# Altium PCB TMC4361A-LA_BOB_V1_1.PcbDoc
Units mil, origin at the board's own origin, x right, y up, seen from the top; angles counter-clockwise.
Board outline 1000 x 1500 mil, 4 copper layers (Top, GND1, GND2, Bottom), stack 27.719 mil thick; 21 components, 35 nets, 88 pads, 56 vias.
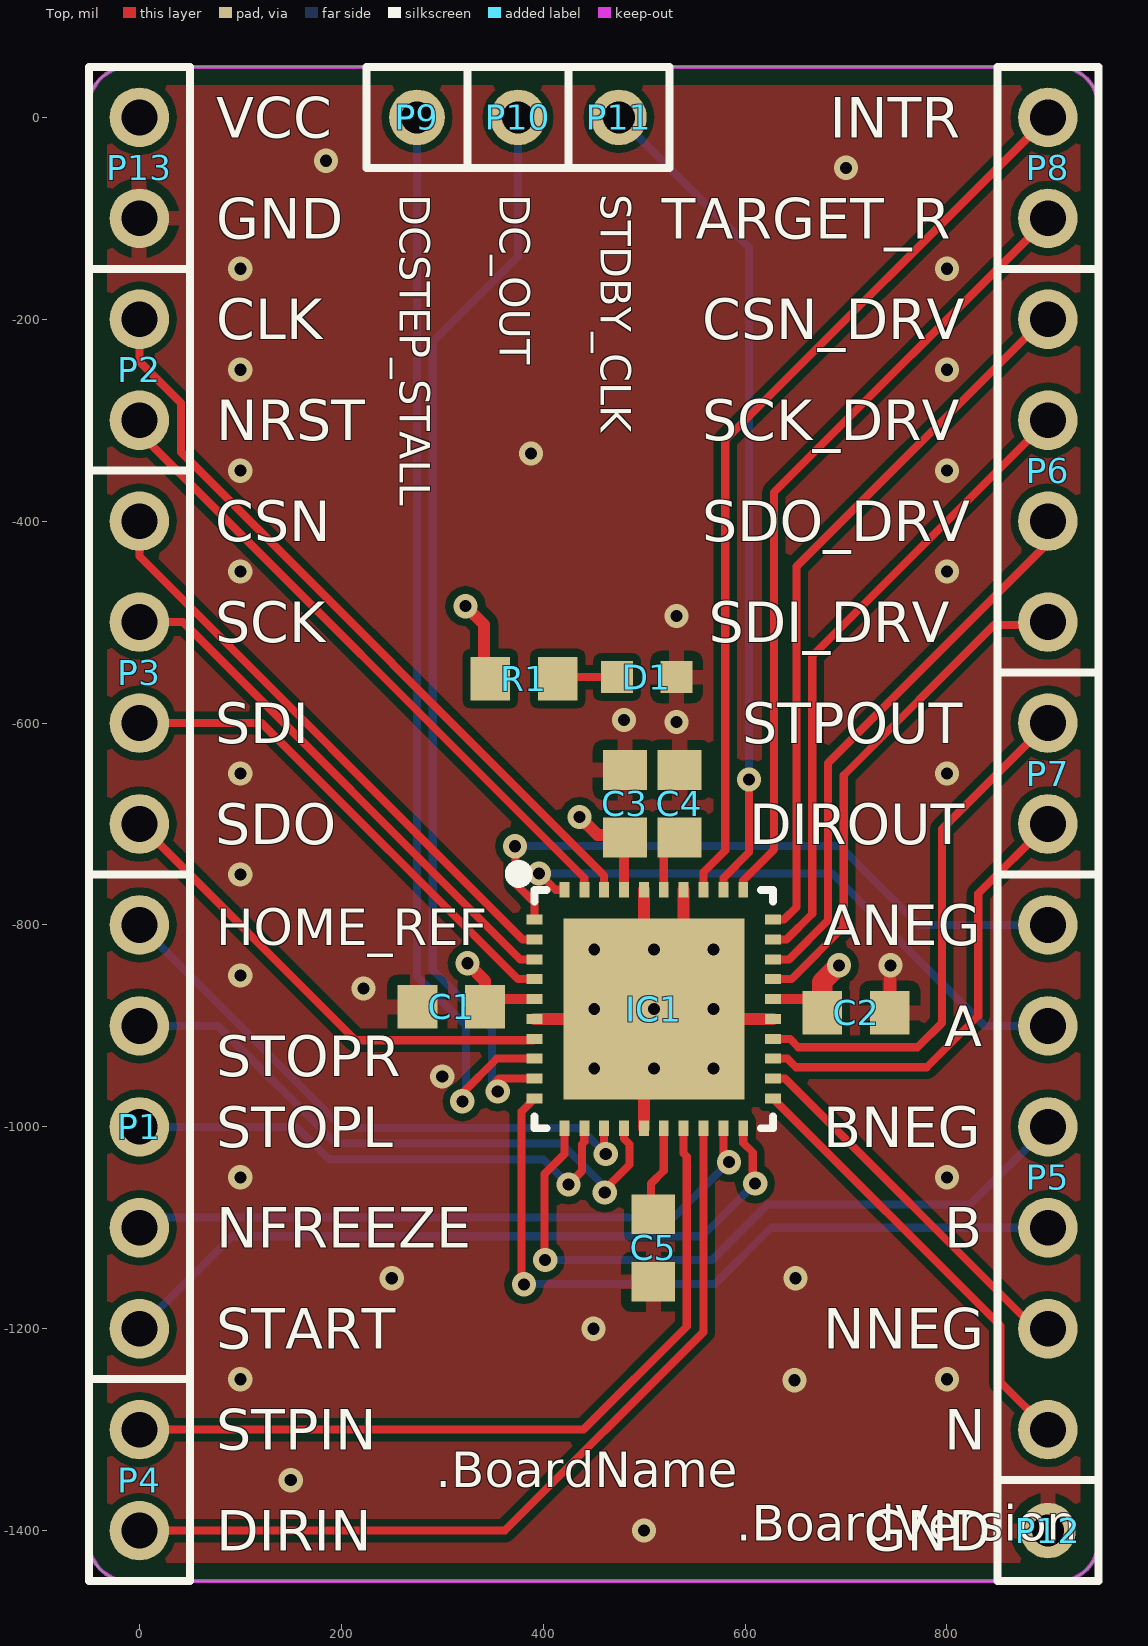
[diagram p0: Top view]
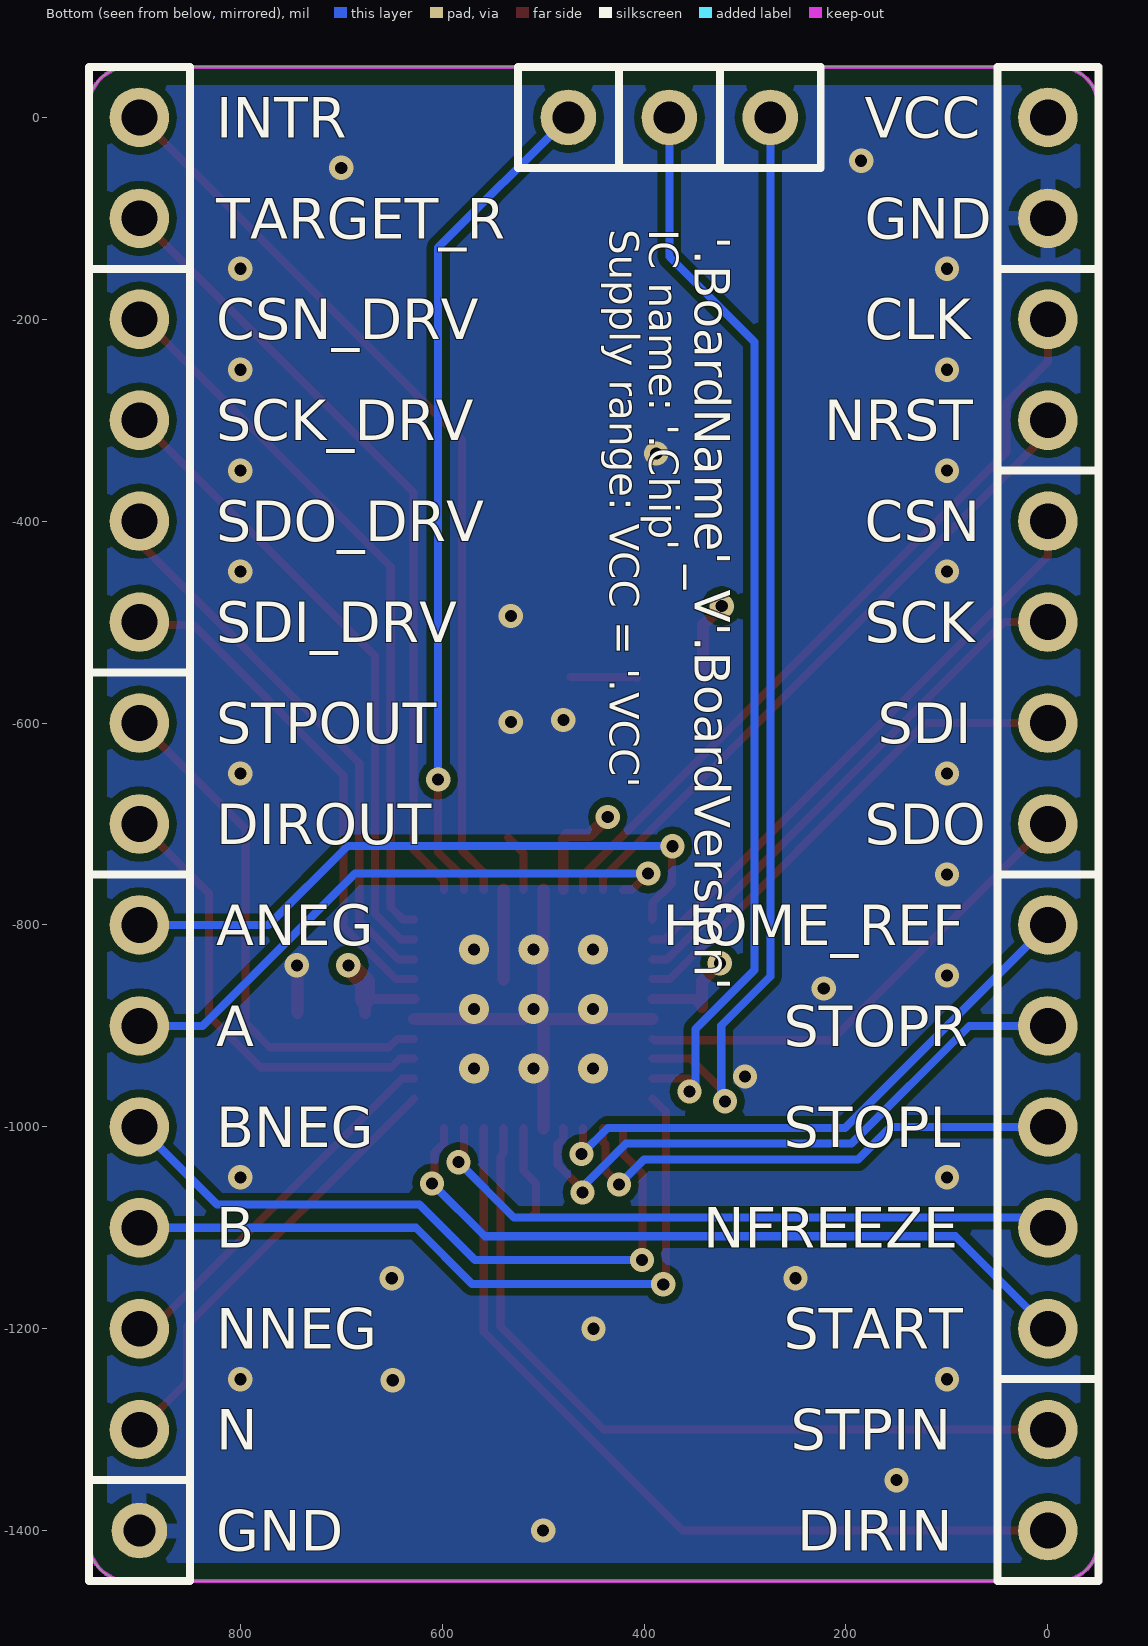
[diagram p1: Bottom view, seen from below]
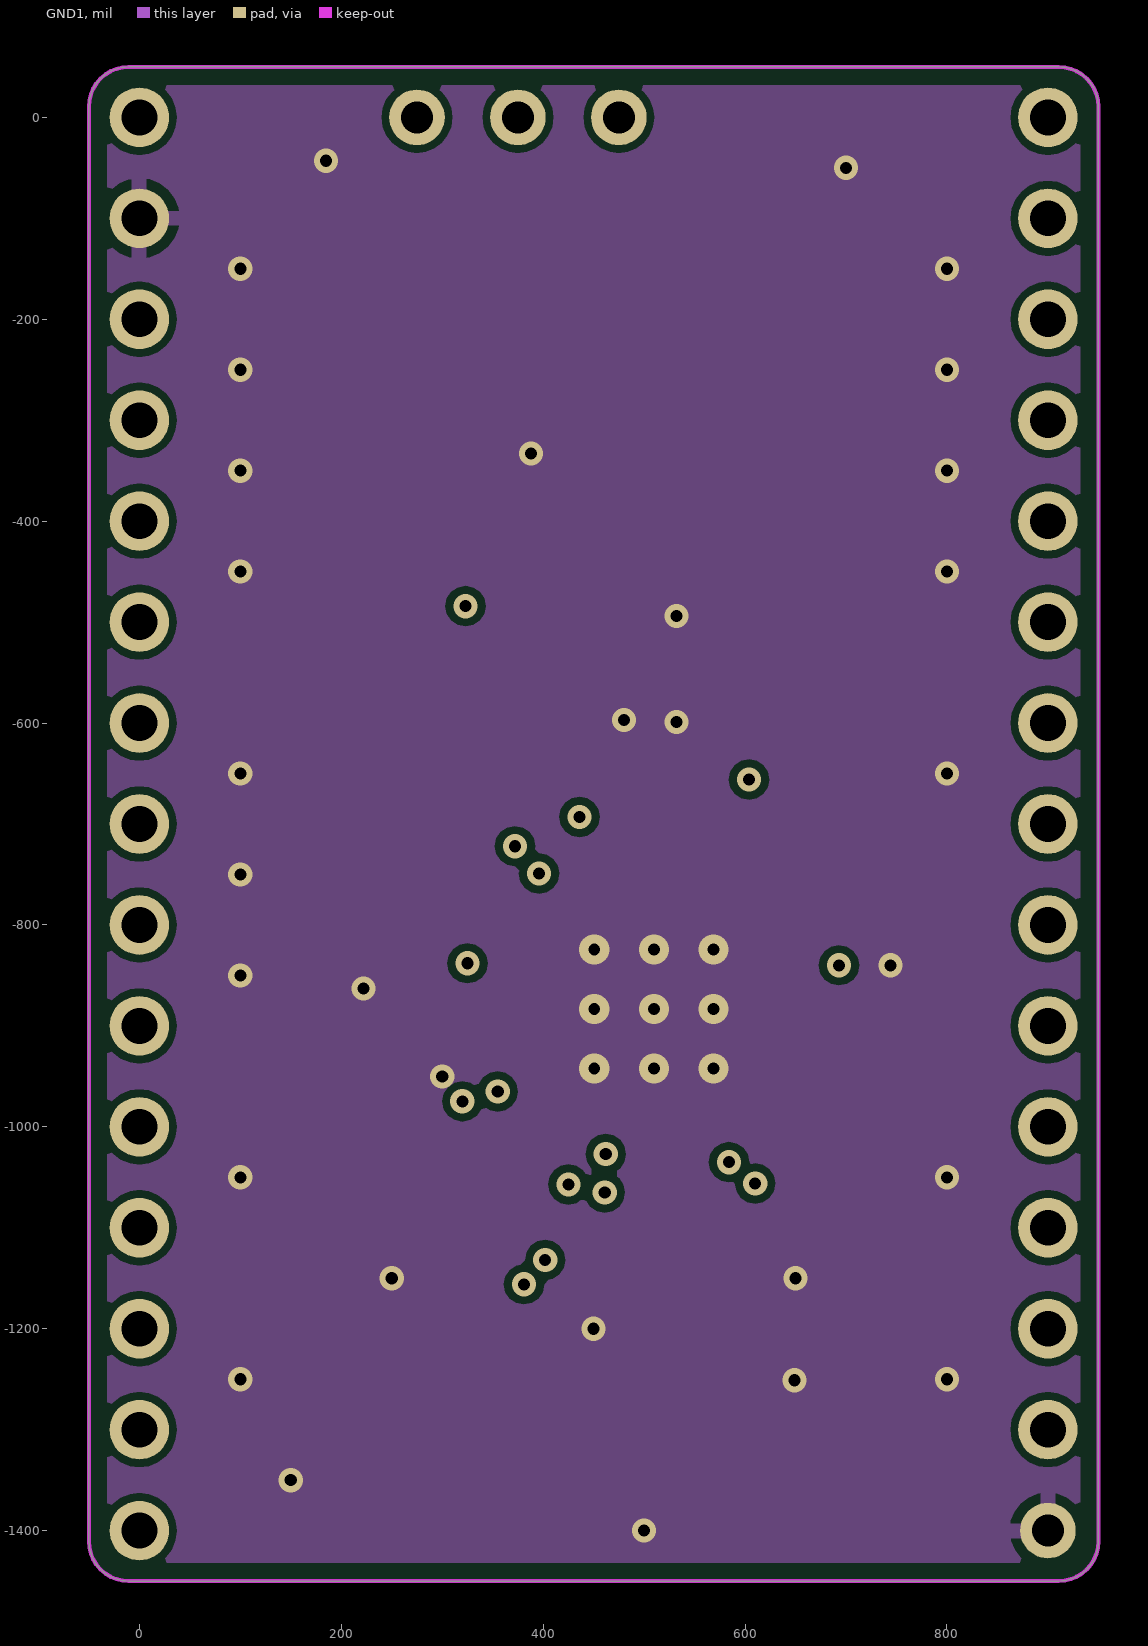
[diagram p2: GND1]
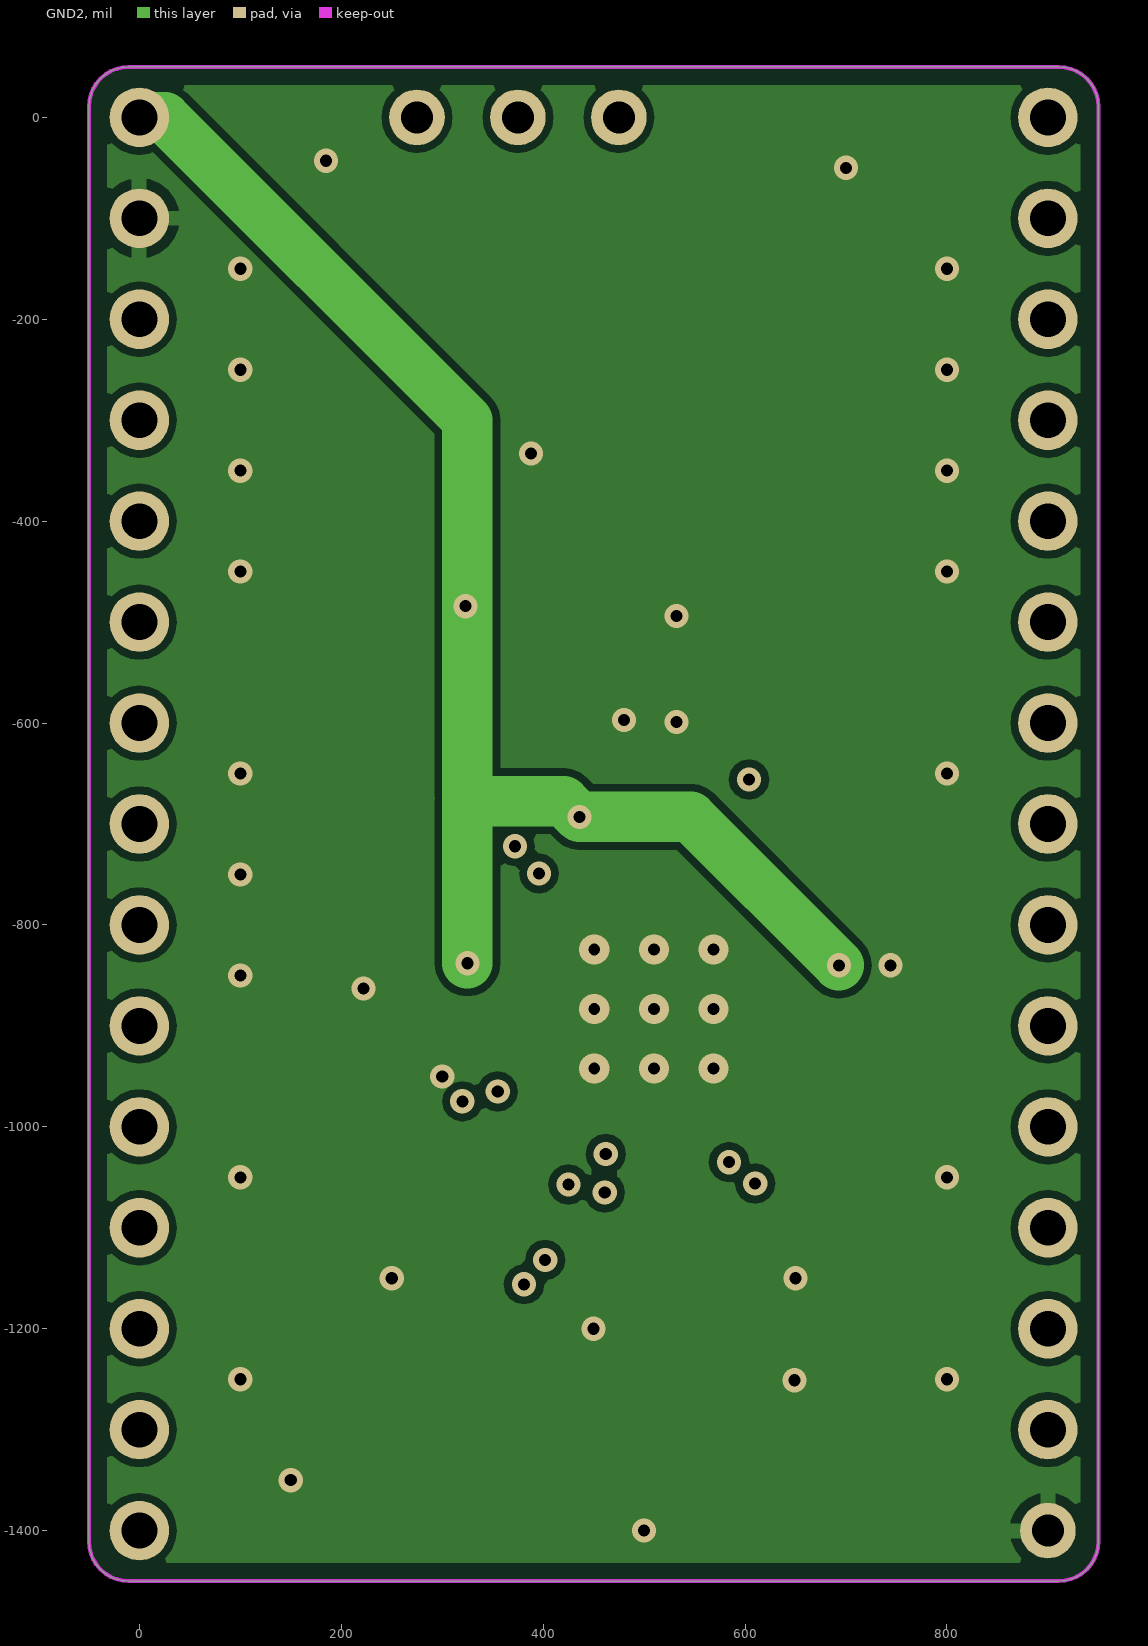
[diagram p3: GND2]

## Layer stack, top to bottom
Top Solder: solder mask 0.4, Solder Resist, Dk 3.5
Top: signal copper 1.378
Dielectric 1: core 7.874, FR-4, Dk 4.8
GND1: signal copper 0.689
Dielectric 2: prepreg 5, FR-4, Dk 4.2
GND2: signal copper 1.4
Dielectric4: core 10, FR-4, Dk 4.2
Bottom: signal copper 1.378
Bottom Solder: solder mask 0.4, Solder Resist, Dk 3.5

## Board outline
-50,-1410.63 -50,10.63 cw(c-10.63,10.63) -10.63,50 910.63,50 cw(c910.63,10.63) 950,10.63 950,-1410.63 cw(c910.63,-1410.63) 910.63,-1450 -10.63,-1450 cw(c-10.63,-1410.63)

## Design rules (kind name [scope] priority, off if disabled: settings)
Clearance BoardOutlineClearance [OnLayer('Keep-Out Layer')] p1: gap=15.75 ignorepadtopadclearanceinfootprint=FALSE except(0: Arc-Hole Track-Hole SMDPad-Hole THPad-Hole Via-Hole Fill-Hole Poly-Hole Region-Hole Text-Hole)
Clearance VM_Clearance [InNet('VM') vs not (InComponent('Q1') or InComponent('Q2') or InComponent('Q3') or InComponent('Q4'))] p2: gap=13 ignorepadtopadclearanceinfootprint=FALSE except(0: Arc-Hole Track-Hole SMDPad-Hole THPad-Hole Via-Hole Fill-Hole Poly-Hole Region-Hole Text-Hole)
Clearance "Fiducial Clearance" [HasFootprint('FIDUCIAL_40MIL')] p3: gap=26 ignorepadtopadclearanceinfootprint=FALSE except(0: Arc-Hole Track-Hole SMDPad-Hole THPad-Hole Via-Hole Fill-Hole Poly-Hole Region-Hole Text-Hole)
Clearance "Mounting Hole Clearance" [(HoleDiameter >= 110) And  IsPad  And ((PadYSize_AllLayers - HoleDiameter)  <=  1)] p4: gap=30 ignorepadtopadclearanceinfootprint=FALSE except(0: Arc-Hole Track-Hole SMDPad-Hole THPad-Hole Via-Hole Fill-Hole Poly-Hole Region-Hole Text-Hole)
Clearance [All] p5: gap=7.6 ignorepadtopadclearanceinfootprint=FALSE except(0: Arc-Hole Track-Hole SMDPad-Hole THPad-Hole Via-Hole Fill-Hole Poly-Hole Region-Hole Text-Hole)
ComponentClearance Pinheader2PinheaderClearance [InComponentClass('Pinheader') vs InComponentClass('Pinheader')] p1: gap=0 collisioncheckmode=3 verticalgap=0 showdistances=FALSE
ComponentClearance [All] p2: gap=10 collisioncheckmode=3 verticalgap=10 showdistances=FALSE
DiffPairsRouting [All] p1 off: maxlimit=10 minlimit=7.5 mostfreqgap=10 toplayer_prefgap=7.5 toplayer_minwidth=7.5 toplayer_maxwidth=7.5 toplayer_prefwidth=7.5 midlayer1_prefgap=7.5 midlayer1_minwidth=7.5 midlayer1_maxwidth=7.5 midlayer1_prefwidth=7.5 midlayer2_mingap=10 midlayer2_minwidth=15 midlayer2_maxwidth=15 midlayer2_prefwidth=15 bottomlayer_prefgap=7.5 bottomlayer_minwidth=7.5 bottomlayer_maxwidth=7.5 bottomlayer_prefwidth=7.5 maxuncoupledlength=500
HoleSize [All] p1: absolutevalues=TRUE maxlimit=100000 minlimit=11.81 maxpercent=80.000 minpercent=20.000
HoleToHoleClearance [All] p1: gap=8 allowstackedmicrovias=TRUE
MatchedLengths "SD_CARD MatchedLengths" [InNetClass('SD_CARD')] p1: tolerance=10 checknetsindiffpair=FALSE checkdiffpairvsdiffpair=TRUE checkxsignals=TRUE checkothers=TRUE
MinimumAnnularRing MinimumViaAnnualRing [All] p1: minimumring=4.92
MinimumSolderMaskSliver STM32_MinimumSolderMaskSliver [(InComponent('STM1') AND InComponent('STM2')) vs (InComponent('STM1') AND InComponent('STM2'))] p1: minsoldermaskwidth=1
MinimumSolderMaskSliver USB_HUB_MinimumSolderMaskSliver [InComponent('USB_HUB')] p2: minsoldermaskwidth=1
MinimumSolderMaskSliver [All] p3 off: minsoldermaskwidth=1.5
PasteMaskExpansion TestPadPasteMaskExpansion [HasFootprint('SMD_TP_2X2_ROUND')] p1: expansion=-78.74
PasteMaskExpansion [All] p2: expansion=0
PlaneConnect VM_PlaneConnect [OnLayer('VM') AND InNet('VM')] p1: planeconnectstyle=Relief reliefexpansion=20 reliefentries=4 reliefconductorwidth=20 reliefairgap=10
PlaneConnect [All] p2: planeconnectstyle=Relief reliefexpansion=20 reliefentries=4 reliefconductorwidth=10 reliefairgap=10
PolygonConnect VSA_C1_ConnectStyle [InNet('VM') AND inComponent('C1')] p1: connectstyle=Direct reliefconductorwidth=20 reliefentries=4 polygonreliefangle="90 Angle" airgapwidth=8
PolygonConnect VSAViaConnectStyle [InNet('VM') AND IsVia] p2: connectstyle=Direct reliefconductorwidth=20 reliefentries=4 polygonreliefangle="90 Angle" airgapwidth=8
PolygonConnect VSAConnectStyle [InNet('VM')] p3: connectstyle=Relief reliefconductorwidth=20 reliefentries=4 polygonreliefangle="90 Angle" airgapwidth=15
PolygonConnect MotorPhaceConnectStyle [(IsVia OR IsPad) AND InNetClass('MotorPower')] p4: connectstyle=Direct reliefconductorwidth=10 reliefentries=4 polygonreliefangle="90 Angle" airgapwidth=10
PolygonConnect ThermalVias [IsVia] p5: connectstyle=Direct reliefconductorwidth=10 reliefentries=4 polygonreliefangle="90 Angle" airgapwidth=10
PolygonConnect [All] p6: connectstyle=Relief reliefconductorwidth=15 reliefentries=4 polygonreliefangle="90 Angle" airgapwidth=10
RoutingVias [All] p1: holewidth=12 width=22 viastyle="Through Hole" minholewidth=12 minwidth=22 maxholewidth=12 maxwidth=50
ShortCircuit [All] p1 off: allowed=FALSE
SilkToBoardRegionClearance [All] p1 off:
SilkToSilkClearance [All] p1 off: silktosilkclearance=10
SilkToSolderMaskClearance [IsPad] p1 off: minsilkscreentomaskgap=10 clearancetoexposedcopper=TRUE
SolderMaskExpansion FiducialSolderMaskExpansion [HasFootprint('FIDUCIAL_40MIL')] p1: expansion=26
SolderMaskExpansion [All] p2: expansion=4
UnRoutedNet [All] p1 off:
Width VIN_Width [InNetClass('PWR_VIN')] p1: maxlimit=300 minlimit=200 preferedwidth=210
Width Other_Width [All] p2: maxlimit=100000 minlimit=8 preferedwidth=11.81 minimp=50.000000 maximp=50.000000 favimp=50.000000
18 further rules are at their usual default settings.

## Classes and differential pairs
differential pair class USB_DIFF: STM_USB STM_USB_D

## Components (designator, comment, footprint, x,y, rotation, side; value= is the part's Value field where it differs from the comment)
C1 "100nF/16V/10%" C0603 309,-881 r180 top
C2 "100nF/16V/10%" C0603 710,-887 r0 top
C3 "100nF/16V/10%" C0603 481,-680 r90 top
C4 "100nF/16V/10%" C0603 535,-680 r90 top
C5 "100nF/16V/10%" C0603 509,-1120 r270 top
D1 "LED, Blue, SMD, 20mA, 2.8V, 465 nm" LED_0603 502.6,-554.5 r0 top
IC1 "TMC4361A-LA" TMC4361A-LA_QFN40_0.5_6.0X6.0 509.64,-883.28 r270 top
P1 "CTL" 5_PIN_THT 0,-800 r180 top
P2 "CLK" 2_PIN_THT 0,-200 r180 top
P3 "SPI" 4_PIN_THT 0,-700 r0 top
P4 "SDIN" 2_PIN_THT 0,-1300 r180 top
P5 "ENC" 6_PIN_THT 900,-800 r180 top
P6 "SPI_DRV" 4_PIN_THT 900,-200 r180 top
P7 "SDOUT" 2_PIN_THT 900,-700 r0 top
P8 "" 2_PIN_THT 900,-100 r0 top
P9 "DCSTEP_STALL" TH_PIN 275,0 r180 top
P10 "DC_OUT" TH_PIN 375,0 r180 top
P11 "STDBY_CLK" TH_PIN 475,0 r180 top
P12 "GND" TH_PIN 900,-1400 r0 top
P13 "PWR" 2_PIN_THT 0,0 r180 top
R1 "1k" R0603 381,-556 r180 top

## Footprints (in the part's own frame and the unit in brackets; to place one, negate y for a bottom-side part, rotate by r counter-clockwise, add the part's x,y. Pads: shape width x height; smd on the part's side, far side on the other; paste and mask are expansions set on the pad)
2_PIN_THT [mm]
  round 1.5 hole 0.9: 1(0,0) 2(0,2.54)
  silkscreen extent -1.27,-1.27 1.27,3.81
4_PIN_THT [mm]
  round 1.5 hole 0.9: 1(0,0) 2(0,2.54) 3(0,5.08) 4(0,7.62)
  silkscreen extent -1.27,-1.27 1.27,8.89
5_PIN_THT [mm]
  round 1.5 hole 0.9: 1(0,0) 2(0,2.54) 3(0,5.08) 4(0,7.62) 5(0,10.16)
  silkscreen extent -1.27,-1.27 1.27,11.43
6_PIN_THT [mm]
  round 1.5 hole 0.9: 1(0,0) 2(0,2.54) 3(0,5.08) 4(0,7.62) 5(0,10.16) 6(0,12.7)
  silkscreen extent -1.27,-1.27 1.27,13.97
C0603 [mm] "0603 ceramic capacitor"
  rect 1x1.1 smd: 1(-0.85,0) 2(0.85,0)
  body extent -0.8,-0.4 0.8,0.4, height 0.8
LED_0603 [mm]
  rect 0.8x0.8 smd: 1(-0.75,0) 2(0.75,0)
  body extent -0.8,-0.38 0.85,0.35, height 0.68
R0603 [mm] "0603 resistor"
  rect 1x1.1 smd: 1(-0.85,0) 2(0.85,0)
  body extent -0.8,-0.4 0.8,0.4, height 0.45
TH_PIN [mm]
  round 1.4 hole 0.8: 1(0,0)
  silkscreen extent -1.27,-1.27 1.27,1.27
TMC4361A-LA_QFN40_0.5_6.0X6.0 [mm]
  rect 0.25x0.4 smd: 1(-2.25,-3) 2(-1.75,-3) 3(-1.25,-3) 4(-0.75,-3) 5(-0.25,-3) 6(0.25,-3) 7(0.75,-3) 8(1.25,-3) 9(1.75,-3) 10(2.25,-3) 21(2.25,3) 22(1.75,3) 23(1.25,3) 24(0.75,3) 25(0.25,3) 26(-0.25,3) 27(-0.75,3) 28(-1.25,3) 29(-1.75,3) 30(-2.25,3)
  rect 0.4x0.25 smd: 11(3,-2.25) 12(3,-1.75) 13(3,-1.25) 14(3,-0.75) 15(3,-0.25) 16(3,0.25) 17(3,0.75) 18(3,1.25) 19(3,1.75) 20(3,2.25) 31(-3,2.25) 32(-3,1.75) 33(-3,1.25) 34(-3,0.75) 35(-3,0.25) 36(-3,-0.25) 37(-3,-0.75) 38(-3,-1.25) 39(-3,-1.75) 40(-3,-2.25)
  rect 4.55x4.55 smd paste-25.4: 41(0,0)
  silkscreen extent -3.5,-3.5 3,3, body extent -3,-3 3,3, height 0.9

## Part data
C1 C2 C3 C4 C5: library part Capacitor, "Ceramic capacitor"
IC1: "S-ramp motion controller for stepper motors with high velocities. With SPI and Step/Dir; QFN40(5x5)"
P1: library part "Header 5", "Header, 5-Pin"
P2 P4 P7 P8 P13: library part "Header 2", "Header, 2-Pin"
P3 P6: library part "Header 4", "Header, 4-Pin"
P5: library part "Header 6", "Header, 6-Pin"
P9 P10 P11 P12: library part PIN
R1: library part "1 kohm, 50 V, 0603 [1608 Metric], 63 mW, ± 1%, MC Series", "1 kohm, 50 V, 0603 [1608 Metric], 63 mW, ± 1%, MC Series"

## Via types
v1: diameter 24, hole 12, Top to Bottom, tented both sides, 47 vias
v2: diameter 29.81, hole 11.81, Top to Bottom, tented both sides, 9 vias

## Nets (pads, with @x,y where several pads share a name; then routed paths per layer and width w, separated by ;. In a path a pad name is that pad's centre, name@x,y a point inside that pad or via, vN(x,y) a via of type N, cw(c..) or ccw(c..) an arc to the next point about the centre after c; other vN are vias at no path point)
A: IC1.40 P5.2 | length 598.3
  Top w8: v1(396,-749) 412.17,-765.17 IC1.40
  Bottom w8: v1(396,-749) 686.38,-749 837.38,-900 P5.2
ANEG: IC1.1 P5.1 | length 641.1
  Top w8: v1(372,-722) 372.4,-722.4 372.4,-758.78 391.53,-777.9 IC1.1
  Bottom w8: v1(372,-722) 694,-722 772,-800 P5.1
B: IC1.10 P5.4 | length 732.9
  Top w8: v1(381,-1156) 378.4,-1153.4 378.4,-984.99 IC1.10
  Bottom w8: v1(381,-1156) 381.4,-1155.6 570.4,-1155.6 626,-1100 P5.4
BNEG: IC1.11 P5.3 | length 691.7
  Top w8: v1(402,-1132) 401.4,-1131.4 401.4,-1046.6 421.06,-1026.94 IC1.11
  Bottom w8: v1(402,-1132) 567.38,-1132 622.38,-1077 823,-1077 P5.3
CLK: IC1.38 P2.1 | length 755.9
  Top w8: P2.1 0,-241.84 41.13,-282.96 41.13,-331.62 460.43,-750.91 IC1.38
CSN: IC1.2 P3.4 | length 583.5
  Top w8: P3.4 0,-434.72 379.65,-814.38 IC1.2
CSN_DRV: IC1.30 P6.1 | length 716.5
  Top w8: IC1.30 638.75,-794.69 651,-782.44 651,-445 P6.1@899,-197
DC_OUT: IC1.9 P10.1 | length 1063.8
  Top w8: v1@349.19,-959.32 356.33,-952.17 IC1.9
  Bottom w8: v1@349.19,-959.32 349.19,-903.13 290.6,-844.54 290.6,-222.4 375,-138 P10.1
  other v1: 355,-965
DCSTEP_STALL: IC1.8 P9.1 | length 1090.3
  Top w8: v1(319.93,-974.75) 319.93,-966.51 353.96,-932.49 IC1.8
  Bottom w8: P9.1 275,-851 323.6,-899.6 323.6,-971.09 v1(319.93,-974.75)
DIRIN: IC1.18 P4.2 | length 842.2
  Top w8: P4.2 362,-1400 558.85,-1203.15 IC1.18
DIROUT: IC1.23 P7.1 | length 446.5
  Top w8: IC1.23 642,-932.49 650.51,-941 780,-941 831,-890 831,-769 P7.1
GND: C1.2 C2.2 C3.2 C4.2 C5.2 D1.2 IC1.6 IC1.15 IC1.25 IC1.34 IC1.36 IC1.41 P12.1 P13.2 | length 582.8
  Top w12: IC1.6 IC1.41@499.8,-893.12 ; IC1.15 IC1.41@499.8,-893.12 ; IC1.41@499.8,-873.43 IC1.36 ; v2(509.63,-883.27) IC1.41@499.8,-893.12 ; IC1.41@519.48,-893.12 IC1.25 ; IC1.41@539.17,-853.75 IC1.34 ; C2.2 743.46,-840.54 v1(744,-840)
  other v1: 500,-1400 150,-1350 649,-1251 100,-1250 800,-1250 450,-1200 250,-1150 650,-1150 100,-1050 800,-1050 300,-950 222,-863 100,-850 100,-750 100,-650 800,-650 532,-599 480,-597 532,-494 100,-450 800,-450 100,-350 800,-350 388,-333 100,-250 800,-250 100,-150 800,-150 700,-50 185,-43
  other v2: 450.58,-942.33 509.64,-942.33 568.69,-942.33 450.58,-883.28 568.69,-883.28 450.58,-824.22 509.64,-824.22 568.69,-824.22
HOME_REF: IC1.13 P1.1 | length 577.8
  Top w8: v1@460,-1023 460.43,-1022.57 IC1.13
  Bottom w8: P1.1 201,-1001 436,-1001 v1(462,-1027)
INTR: IC1.33 P8.2 | length 906.5
  Top w8: IC1.33 558.85,-747.77 580.4,-726.22 580.4,-319.6 P8.2
N: IC1.21 P5.6 | length 440.9
  Top w8: IC1.21 853,-1197.11 853,-1253 P5.6
NetD1_1: D1.1 R1.1 | length 66.5
  Top w8: R1.1@407,-555.46 407.96,-554.5 D1.1
NFREEZE: IC1.19 P1.4 | length 646.8
  Top w8: IC1.19 578.54,-1029.54 v1(584,-1035)
  Bottom w8: P1.4 10,-1090 529,-1090 v1(584,-1035)
NNEG: IC1.22 P5.5 | length 374.9
  Top w8: IC1.22 639.62,-952.17 887.45,-1200 P5.5
NRST: IC1.39 P2.2 | length 647.7
  Top w8: P2.2 0,-312.55 440.74,-753.29 IC1.39
SCK: IC1.3 P3.3 | length 529.9
  Top w8: P3.3 43.21,-500 377.28,-834.06 IC1.3
SCK_DRV: IC1.29 P6.2 | length 635
  Top w8: IC1.29 641.12,-814.38 666.6,-788.9 666.6,-533.4 P6.2
SDI: IC1.4 P3.2 | length 496.6
  Top w8: P3.2 121.15,-600 374.9,-853.75 IC1.4
SDI_DRV: IC1.27 P6.4 | length 506.7
  Top w8: IC1.27 645.88,-853.75 697.8,-801.82 697.8,-651.72 846.52,-503 897,-503 P6.4
SDO: IC1.7 P3.1 | length 480.9
  Top w8: P3.1 214.25,-914.25 390.08,-914.25 IC1.7
SDO_DRV: IC1.28 P6.3 | length 556.1
  Top w8: IC1.28 643.5,-834.06 682.2,-795.36 682.2,-639.48 900,-421.68 P6.3
START: IC1.20 P1.5 | length 729.1
  Top w8: IC1.20 598.22,-1015.85 607.6,-1025.22 607.6,-1053.6 v1(610,-1056)
  Bottom w8: P1.5 91.6,-1108.4 557.6,-1108.4 v1(610,-1056)
STDBY_CLK: IC1.32 P11.1 | length 829.1
  Top w8: IC1.32 578.54,-753.46 604,-728 v1(604,-656)
  Bottom w8: P11.1 604,-129 v1(604,-656)
STOPL: IC1.12 P1.3 | length 510.7
  Top w8: v1(425,-1057) 438.4,-1043.6 438.4,-1017.22 440.74,-1014.88 IC1.12
  Bottom w8: P1.3 155.88,-1000 188.08,-1032.2 400.2,-1032.2 v1(425,-1057)
STOPR: IC1.14 P1.2 | length 608.6
  Top w8: v1(461,-1065) 461,-1062.15 485.6,-1037.55 485.6,-1017.22 480.11,-1011.73 IC1.14
  Bottom w8: P1.2 77.94,-900 194.54,-1016.6 417.98,-1016.6 461,-1059.62 v1(461,-1065)
STPIN: IC1.17 P4.1 | length 782.2
  Top w8: P4.1 439.94,-1300 542.25,-1197.68 542.25,-1029.25 539.17,-1026.17 IC1.17
STPOUT: IC1.24 P7.2 | length 521.2
  Top w8: IC1.24 644.38,-912.8 652.7,-921.13 770.87,-921.13 795,-897 795,-705 P7.2
TARGET_R: IC1.31 P8.1 | length 790.2
  Top w8: IC1.31 598.22,-755.84 628.6,-725.46 628.6,-371.4 P8.1
VCC: C1.1 C2.1 C3.1 IC1.5 IC1.26 IC1.37 P13.1 R1.2 | length 1805.5
  Top w8: C3.1@476.76,-711 C3.1@480.11,-714.35
  Top w10: C1.1 350.03,-873.43 IC1.5 ; IC1.37 C3.1@480.11,-714.35 ; IC1.26 C2.1@676.54,-873.43
  Top w12: v1(323.07,-484.18) 341.54,-502.65 R1.2@341.54,-556 ; v1(325,-838) 342.46,-855.46 C1.1 ; v1(436,-693) 454,-711 C3.1@476.76,-711 ; C2.1 C2.1@676.54,-873.43
  Top w20: C2.1@676.54,-873.43 676.54,-856.46 v1(693,-840)
  GND2 w50: P13.1 25,0 325,-300 325,-672 ; v1(325,-838) 325,-677.4 420.4,-677.4 v1(436,-693) 546,-693 v1(693,-840)
VDD1V8_1: C5.1 IC1.16 | length 91.1
  Top w8: C5.1 507,-1084.54 507,-1056 519.48,-1043.52 IC1.16
VDD1V8_2: C4.1 IC1.35 | length 58.1
  Top w8: IC1.35 519.48,-728.98 C4.1

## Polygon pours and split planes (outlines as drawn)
GND on Bottom "BTM_GND" (solid, pour order 52): 910.63,-1450 -10.63,-1450 cw(c-10.63,-1410.63) -50,-1410.63 -50,10.63 cw(c-10.63,10.63) -10.63,50 910.63,50 cw(c910.63,10.63) 950,10.63 950,-1410.63 cw(c910.63,-1410.63)
GND on Top "TOP_GND" (solid, pour order 49): 910.63,-1450 -10.63,-1450 cw(c-10.63,-1410.63) -50,-1410.63 -50,10.63 cw(c-10.63,10.63) -10.63,50 910.63,50 cw(c910.63,10.63) 950,10.63 950,-1410.63 cw(c910.63,-1410.63)
GND on GND1 "GND_GND" (solid, pour order 47): 910.63,-1450 -10.63,-1450 cw(c-10.63,-1410.63) -50,-1410.63 -50,10.63 cw(c-10.63,10.63) -10.63,50 910.63,50 cw(c910.63,10.63) 950,10.63 950,-1410.63 cw(c910.63,-1410.63)
GND on GND2 "VM_VM" (solid, pour order 45): 910.63,-1450 -10.63,-1450 cw(c-10.63,-1410.63) -50,-1410.63 -50,10.63 cw(c-10.63,10.63) -10.63,50 910.63,50 cw(c910.63,10.63) 950,10.63 950,-1410.63 cw(c910.63,-1410.63)

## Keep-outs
Keep-Out Layer:
  the board outline again, w4

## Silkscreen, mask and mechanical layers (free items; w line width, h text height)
Top Overlay:
  text "VCC" at 76,-19.99 h40
  text "INTR" at 684.05,-19.99 h40
  text "GND" at 76,-119.99 h40
  text "TARGET_R" at 517.43,-119.99 h40
  text "CLK" at 76,-219.99 h40
  text "CSN_DRV" at 557.42,-219.99 h40
  text "NRST" at 76,-319.99 h40
  text "SCK_DRV" at 557.42,-319.99 h40
  text "CSN" at 75,-419.99 h40
  text "SDO_DRV" at 557.42,-419.99 h40
  text "SCK" at 75,-519.99 h40
  text "SDI_DRV" at 564.08,-519.99 h40
  text "SDI" at 75,-619.99 h40
  text "STPOUT" at 597.41,-619.99 h40
  text "SDO" at 75,-719.99 h40
  text "DIROUT" at 604.07,-719.99 h40
  text "HOME_REF" at 76,-819.99 h36
  text "ANEG" at 677.38,-819.99 h40
  text "A" at 797.34,-919.99 h40
  text "STOPR" at 76,-950 h40
  text "STOPL" at 76,-1019.99 h40
  text "BNEG" at 677.38,-1019.99 h40
  text "NFREEZE" at 76,-1119.99 h40
  text "B" at 797.34,-1119.99 h40
  text "START" at 76,-1219.99 h40
  text "NNEG" at 677.38,-1219.99 h40
  text "STPIN" at 76,-1319.99 h40
  text "N" at 797.34,-1319.99 h40
  text ".BoardName" at 293.76,-1356.94 h35
  text ".BoardVersion" at 591.16,-1410 h35
  text "DIRIN" at 76,-1419.99 h40
  text "GND" at 717.37,-1419.99 h40
Bottom Overlay:
  text "VCC" at 181.63,-19.99 h40
  text "INTR" at 824,-19.99 h40
  text "IC name: '.Chip'" at 405,-111 h50 r90
  text "Supply range: VCC = '.VCC'" at 444.05,-110.9 h50 r90
  text "'.BoardName'_V'.BoardVersion'" at 350,-118 h35 r90
  text "GND" at 181.63,-119.99 h40
  text "TARGET_R" at 824,-119.99 h40
  text "CLK" at 181.63,-219.99 h40
  text "CSN_DRV" at 824,-219.99 h40
  text "NRST" at 221.62,-319.99 h40
  text "SCK_DRV" at 824,-319.99 h40
  text "CSN" at 181.63,-419.99 h40
  text "SDO_DRV" at 824,-419.99 h40
  text "SCK" at 181.63,-519.99 h40
  text "SDI_DRV" at 824,-519.99 h40
  text "SDI" at 168.3,-619.99 h40
  text "STPOUT" at 824,-619.99 h40
  text "SDO" at 181.63,-719.99 h40
  text "DIROUT" at 824,-719.99 h40
  text "HOME_REF" at 381.57,-819.99 h40
  text "ANEG" at 824,-819.99 h40
  text "STOPR" at 261.61,-919.99 h40
  text "A" at 824,-919.99 h40
  text "STOPL" at 261.61,-1019.99 h40
  text "BNEG" at 824,-1019.99 h40
  text "NFREEZE" at 341.58,-1119.99 h40
  text "B" at 824,-1119.99 h40
  text "START" at 261.61,-1219.99 h40
  text "NNEG" at 824,-1219.99 h40
  text "STPIN" at 254.94,-1319.99 h40
  text "N" at 824,-1319.99 h40
  text "DIRIN" at 248.28,-1419.99 h40
  text "GND" at 824,-1419.99 h40
TopAsm:
  text ".BoardName" at 185,-1325 h50
  text ".BoardVersion" at 600,-1400 h50

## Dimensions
950,10.63 to -50,10.63 on Dimension
-10.63,-1450 to 910.63,50 on Dimension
